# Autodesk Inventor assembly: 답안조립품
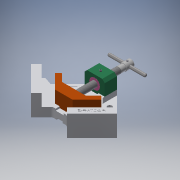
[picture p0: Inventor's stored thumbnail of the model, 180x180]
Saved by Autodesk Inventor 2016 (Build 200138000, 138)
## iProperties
Created: 2019-04
Part Number: 답안조립품
Material: 일반
Document SubType Name: Assembly
Designer: 605-06
Author: 605-06
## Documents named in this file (11)
- C:\Users\605-06\Desktop\490408V1007\답안조립품.iam
- C:\Users\605-06\Desktop\490408V1007\베이스.ipt
- C:\Users\605-06\Desktop\490408V1007\리드스크류.ipt
- C:\Users\605-06\Desktop\490408V1007\부시.ipt
- C:\Users\605-06\Desktop\490408V1007\서포트.ipt
- C:\Users\605-06\Desktop\490408V1007\조.ipt
- C:\Users\605-06\Desktop\490408V1007\평행 핀 2.5x24.ipt
- C:\Users\605-06\Desktop\490408V1007\핸들.ipt
- C:\Users\605-06\Desktop\490408V1007\멈춤나사 M4x5.ipt
- C:\Users\605-06\Desktop\490408V1007\멈춤나사 M4x10.ipt
- C:\Users\605-06\Desktop\490408V1007\볼트 M4x16.ipt
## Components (1 placed, 1 different names)
1. 핸들:1
